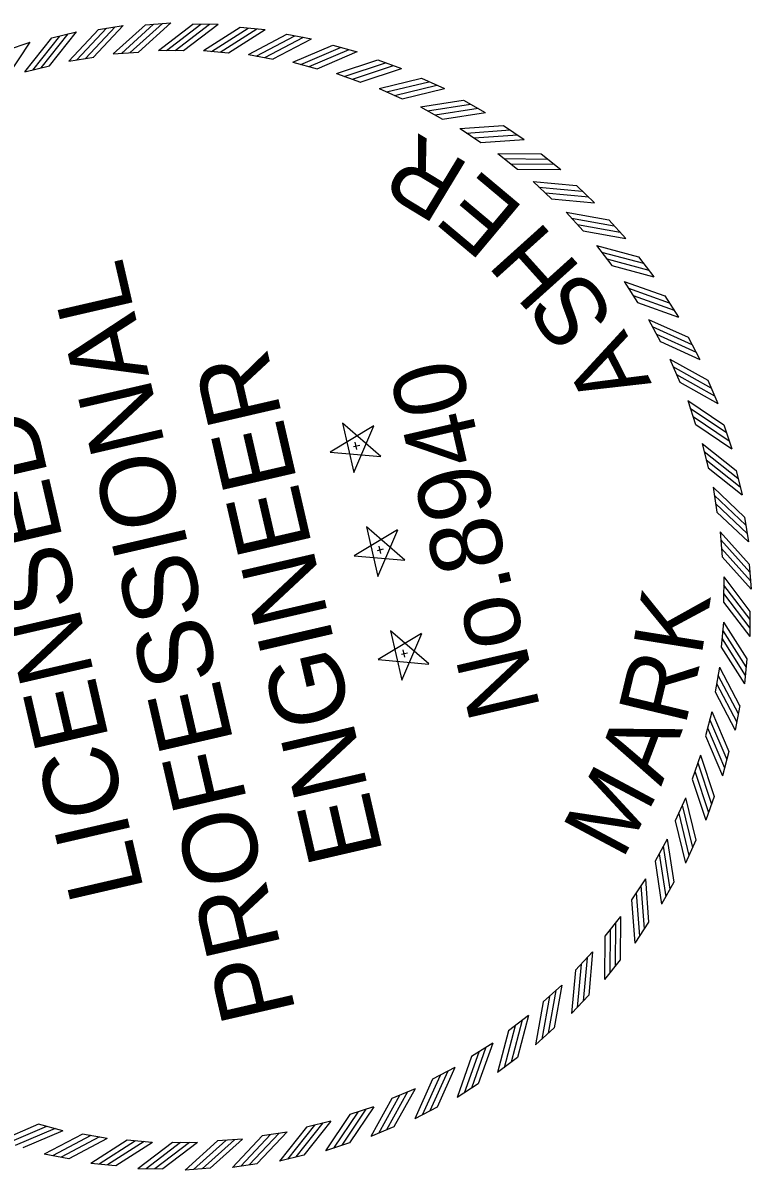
# Model space of a CAD drawing. Extents: x 634644 to 1109508, y 286699 to 700437.
# Drawn here: x 1108220.4 to 1108286.1, y 700312.5 to 700415.8 of the extents above; entities that cross this region are included whole.
import ezdxf

# ---------------------------------------------------------------- set-up
doc = ezdxf.new("R2010")
doc.units = 0
doc.layers.add('R_Border', color=7, linetype='Continuous')

msp = doc.modelspace()

# ---------------------------------------------------------------- linework, layer by layer
at = {"layer": 'R_Border'}
for p, q in [((1108223.06, 700414.47), (1108225.26, 700415)), ((1108227.26, 700415.23), (1108229.49, 700415.58)), ((1108231.5, 700415.65), (1108233.76, 700415.81)), ((1108235.76, 700415.72), (1108238.03, 700415.69)), ((1108240.02, 700415.43), (1108242.27, 700415.21)), ((1108218.95, 700413.36), (1108221.09, 700414.07)), ((1108244.23, 700414.79), (1108246.46, 700414.39)), ((1108228.59, 700413.03), (1108230.85, 700413.19)), ((1108232.65, 700413.35), (1108234.92, 700413.32)), ((1108236.72, 700413.32), (1108238.98, 700413.11)), ((1108240.77, 700412.96), (1108243, 700412.56)), ((1108248.38, 700413.81), (1108250.57, 700413.22)), ((1108220.62, 700411.41), (1108222.83, 700411.94)), ((1108224.57, 700412.38), (1108226.82, 700412.73)), ((1108244.78, 700412.27), (1108246.97, 700411.69)), ((1108252.44, 700412.48), (1108254.57, 700411.72)), ((1108248.72, 700411.25), (1108250.86, 700410.49)), ((1108256.37, 700410.83), (1108258.43, 700409.9)), ((1108252.56, 700409.91), (1108254.63, 700408.97)), ((1108260.15, 700408.86), (1108262.12, 700407.76)), ((1108256.28, 700408.25), (1108258.26, 700407.15)), ((1108259.85, 700406.3), (1108261.73, 700405.04)), ((1108263.75, 700406.58), (1108265.63, 700405.32)), ((1108263.24, 700404.05), (1108265.01, 700402.64)), ((1108267.15, 700404.01), (1108268.92, 700402.6)), ((1108266.44, 700401.54), (1108268.09, 700399.98)), ((1108270.33, 700401.17), (1108271.98, 700399.62)), ((1108269.42, 700398.76), (1108270.93, 700397.08)), ((1108273.27, 700398.08), (1108274.78, 700396.39)), ((1108272.16, 700395.76), (1108273.53, 700393.95)), ((1108275.94, 700394.75), (1108277.31, 700392.95)), ((1108274.64, 700392.53), (1108275.85, 700390.62)), ((1108278.32, 700391.22), (1108279.54, 700389.31)), ((1108276.84, 700389.11), (1108277.9, 700387.1)), ((1108280.41, 700387.5), (1108281.46, 700385.5)), ((1108278.76, 700385.52), (1108279.65, 700383.44)), ((1108282.18, 700383.62), (1108283.07, 700381.54)), ((1108280.37, 700381.79), (1108281.08, 700379.63)), ((1108249.26, 700379.76), (1108250.28, 700375.31)), ((1108252.7, 700376.76), (1108249.26, 700379.76)), ((1108252.07, 700379.51), (1108248.15, 700377.16)), ((1108250.28, 700375.31), (1108252.07, 700379.51)), ((1108283.63, 700379.61), (1108284.34, 700377.46)), ((1108250.24, 700377.65), (1108250.8, 700377.78)), ((1108250.55, 700377.38), (1108250.4, 700378.04)), ((1108281.67, 700377.93), (1108282.2, 700375.73)), ((1108248.15, 700377.16), (1108252.7, 700376.76)), ((1108284.74, 700375.49), (1108285.27, 700373.29)), ((1108282.65, 700373.98), (1108283, 700371.74)), ((1108285.5, 700371.3), (1108285.85, 700369.06)), ((1108254.22, 700370.16), (1108250.31, 700367.81)), ((1108251.41, 700370.41), (1108252.44, 700365.96)), ((1108254.86, 700367.41), (1108251.41, 700370.41)), ((1108252.44, 700365.96), (1108254.23, 700370.16)), ((1108283.3, 700369.96), (1108283.46, 700367.7)), ((1108252.4, 700368.3), (1108252.96, 700368.43)), ((1108252.71, 700368.03), (1108252.56, 700368.69)), ((1108250.31, 700367.81), (1108254.86, 700367.41)), ((1108285.92, 700367.05), (1108286.08, 700364.8)), ((1108283.61, 700365.91), (1108283.59, 700363.64)), ((1108285.98, 700362.79), (1108285.96, 700360.53)), ((1108283.59, 700361.84), (1108283.38, 700359.58)), ((1108256.38, 700360.81), (1108252.47, 700358.46)), ((1108253.57, 700361.06), (1108254.6, 700356.61)), ((1108257.02, 700358.07), (1108253.57, 700361.06)), ((1108254.6, 700356.61), (1108256.39, 700360.81)), ((1108254.56, 700358.95), (1108255.12, 700359.08)), ((1108254.87, 700358.68), (1108254.72, 700359.34)), ((1108252.47, 700358.46), (1108257.02, 700358.06)), ((1108285.69, 700358.54), (1108285.48, 700356.29)), ((1108283.23, 700357.78), (1108282.83, 700355.55)), ((1108285.06, 700354.32), (1108284.66, 700352.1)), ((1108282.54, 700353.77), (1108281.96, 700351.58)), ((1108281.52, 700349.84), (1108280.76, 700347.7)), ((1108284.07, 700350.17), (1108283.49, 700347.99)), ((1108280.18, 700345.99), (1108279.24, 700343.93)), ((1108282.75, 700346.12), (1108281.99, 700343.99)), ((1108278.52, 700342.28), (1108277.42, 700340.3)), ((1108281.1, 700342.19), (1108280.16, 700340.13)), ((1108276.56, 700338.71), (1108275.3, 700336.83)), ((1108279.12, 700338.41), (1108278.02, 700336.43)), ((1108274.32, 700335.32), (1108272.91, 700333.54)), ((1108276.84, 700334.81), (1108275.59, 700332.93)), ((1108271.8, 700332.12), (1108270.25, 700330.47)), ((1108274.28, 700331.4), (1108272.87, 700329.63)), ((1108269.03, 700329.14), (1108267.34, 700327.62)), ((1108271.44, 700328.22), (1108269.89, 700326.58)), ((1108266.02, 700326.4), (1108264.22, 700325.03)), ((1108268.34, 700325.29), (1108266.66, 700323.77)), ((1108262.8, 700323.92), (1108260.88, 700322.7)), ((1108265.02, 700322.62), (1108263.22, 700321.25)), ((1108259.38, 700321.71), (1108257.37, 700320.66)), ((1108255.79, 700319.8), (1108253.7, 700318.91)), ((1108261.49, 700320.23), (1108259.58, 700319.02)), ((1108252.05, 700318.18), (1108249.9, 700317.47)), ((1108257.77, 700318.15), (1108255.76, 700317.09)), ((1108248.2, 700316.88), (1108245.99, 700316.35)), ((1108224.04, 700316.02), (1108221.85, 700316.6)), ((1108228.05, 700315.32), (1108225.82, 700315.72)), ((1108244.25, 700315.9), (1108242.01, 700315.56)), ((1108253.89, 700316.37), (1108251.81, 700315.49)), ((1108232.1, 700314.97), (1108229.85, 700315.18)), ((1108236.17, 700314.94), (1108233.91, 700314.97)), ((1108240.23, 700315.26), (1108237.97, 700315.1)), ((1108249.88, 700314.93), (1108247.73, 700314.22)), ((1108224.59, 700313.5), (1108222.36, 700313.9)), ((1108245.76, 700313.82), (1108243.56, 700313.29)), ((1108228.8, 700312.86), (1108226.55, 700313.08)), ((1108233.06, 700312.57), (1108230.8, 700312.6)), ((1108237.32, 700312.64), (1108235.07, 700312.48)), ((1108241.56, 700313.05), (1108239.33, 700312.71))]:
    msp.add_line(p, q, dxfattribs=at)
for points in [[(1108222.83, 700411.94), (1108225.26, 700415)], [(1108224.57, 700412.38), (1108227.25, 700415.23)], [(1108225.29, 700412.49), (1108227.98, 700415.34)], [(1108226.07, 700412.62), (1108228.75, 700415.47)], [(1108226.81, 700412.73), (1108229.49, 700415.58)], [(1108228.59, 700413.03), (1108231.5, 700415.65)], [(1108229.32, 700413.07), (1108232.22, 700415.69)], [(1108230.1, 700413.15), (1108233.01, 700415.77)], [(1108230.85, 700413.19), (1108233.76, 700415.81)], [(1108232.65, 700413.34), (1108235.76, 700415.71)], [(1108233.37, 700413.33), (1108236.49, 700415.7)], [(1108234.16, 700413.34), (1108237.27, 700415.71)], [(1108234.91, 700413.32), (1108238.03, 700415.69)], [(1108236.72, 700413.32), (1108240.01, 700415.43)], [(1108237.44, 700413.25), (1108240.74, 700415.35)], [(1108238.22, 700413.19), (1108241.52, 700415.29)], [(1108238.97, 700413.11), (1108242.27, 700415.22)], [(1108218.92, 700410.82), (1108221.1, 700414.07)], [(1108220.62, 700411.4), (1108223.06, 700414.47)], [(1108221.33, 700411.57), (1108223.77, 700414.63)], [(1108222.09, 700411.77), (1108224.53, 700414.83)], [(1108240.77, 700412.96), (1108244.23, 700414.79)], [(1108241.48, 700412.83), (1108244.95, 700414.65)], [(1108242.26, 700412.71), (1108245.72, 700414.53)], [(1108243, 700412.57), (1108246.46, 700414.39)], [(1108244.78, 700412.27), (1108248.38, 700413.8)], [(1108245.48, 700412.08), (1108249.08, 700413.61)], [(1108246.24, 700411.89), (1108249.84, 700413.43)], [(1108246.97, 700411.69), (1108250.57, 700413.23)], [(1108248.72, 700411.25), (1108252.43, 700412.48)], [(1108249.4, 700411), (1108253.12, 700412.23)], [(1108250.15, 700410.75), (1108253.86, 700411.98)], [(1108250.85, 700410.49), (1108254.57, 700411.72)], [(1108252.56, 700409.91), (1108256.36, 700410.83)], [(1108253.22, 700409.6), (1108257.02, 700410.52)], [(1108253.94, 700409.29), (1108257.75, 700410.21)], [(1108254.62, 700408.98), (1108258.43, 700409.9)], [(1108256.28, 700408.25), (1108260.14, 700408.86)], [(1108256.91, 700407.89), (1108260.78, 700408.5)], [(1108257.6, 700407.53), (1108261.47, 700408.13)], [(1108258.26, 700407.15), (1108262.13, 700407.76)], [(1108259.84, 700406.3), (1108263.75, 700406.58)], [(1108260.44, 700405.89), (1108264.35, 700406.17)], [(1108261.11, 700405.46), (1108265.01, 700405.74)], [(1108261.73, 700405.04), (1108265.63, 700405.32)], [(1108263.24, 700404.05), (1108267.15, 700404.01)], [(1108263.8, 700403.59), (1108267.72, 700403.55)], [(1108264.43, 700403.12), (1108268.34, 700403.08)], [(1108265.01, 700402.64), (1108268.93, 700402.6)], [(1108266.43, 700401.54), (1108270.33, 700401.17)], [(1108266.96, 700401.03), (1108270.86, 700400.67)], [(1108267.54, 700400.51), (1108271.44, 700400.14)], [(1108268.09, 700399.98), (1108271.98, 700399.62)], [(1108269.41, 700398.76), (1108273.27, 700398.08)], [(1108269.89, 700398.22), (1108273.75, 700397.53)], [(1108270.43, 700397.65), (1108274.29, 700396.96)], [(1108270.93, 700397.08), (1108274.78, 700396.39)], [(1108272.15, 700395.76), (1108275.94, 700394.75)], [(1108272.59, 700395.17), (1108276.37, 700394.17)], [(1108273.08, 700394.56), (1108276.86, 700393.55)], [(1108273.53, 700393.95), (1108277.31, 700392.95)], [(1108274.63, 700392.53), (1108278.32, 700391.22)], [(1108275.02, 700391.91), (1108278.71, 700390.6)], [(1108275.46, 700391.26), (1108279.14, 700389.95)], [(1108275.85, 700390.62), (1108279.54, 700389.31)], [(1108276.84, 700389.11), (1108280.41, 700387.5)], [(1108277.17, 700388.47), (1108280.74, 700386.85)], [(1108277.55, 700387.78), (1108281.12, 700386.17)], [(1108277.9, 700387.11), (1108281.47, 700385.5)], [(1108278.76, 700385.52), (1108282.18, 700383.62)], [(1108279.04, 700384.85), (1108282.46, 700382.95)], [(1108279.36, 700384.13), (1108282.78, 700382.23)], [(1108279.65, 700383.44), (1108283.07, 700381.54)], [(1108280.37, 700381.79), (1108283.62, 700379.61)], [(1108280.59, 700381.1), (1108283.85, 700378.92)], [(1108280.86, 700380.35), (1108284.11, 700378.18)], [(1108281.09, 700379.64), (1108284.34, 700377.46)], [(1108281.67, 700377.93), (1108284.73, 700375.5)], [(1108281.84, 700377.22), (1108284.9, 700374.79)], [(1108282.04, 700376.46), (1108285.1, 700374.03)], [(1108282.21, 700375.73), (1108285.27, 700373.29)], [(1108282.65, 700373.98), (1108285.5, 700371.3)], [(1108282.75, 700373.26), (1108285.6, 700370.58)], [(1108282.89, 700372.49), (1108285.74, 700369.81)], [(1108283, 700371.74), (1108285.85, 700369.06)], [(1108283.3, 700369.97), (1108285.92, 700367.06)], [(1108283.34, 700369.24), (1108285.96, 700366.33)], [(1108283.41, 700368.46), (1108286.03, 700365.55)], [(1108283.46, 700367.71), (1108286.08, 700364.8)], [(1108283.61, 700365.91), (1108285.98, 700362.79)], [(1108283.59, 700365.18), (1108285.96, 700362.07)], [(1108283.6, 700364.4), (1108285.97, 700361.28)], [(1108283.59, 700363.64), (1108285.96, 700360.53)], [(1108283.59, 700361.84), (1108285.69, 700358.54)], [(1108283.46, 700360.33), (1108285.56, 700357.03)], [(1108283.51, 700361.12), (1108285.62, 700357.82)], [(1108283.38, 700359.58), (1108285.48, 700356.28)], [(1108283.09, 700357.07), (1108284.92, 700353.61)], [(1108283.23, 700357.79), (1108285.05, 700354.33)], [(1108282.97, 700356.3), (1108284.8, 700352.83)], [(1108282.83, 700355.56), (1108284.66, 700352.09)], [(1108282.34, 700353.08), (1108283.88, 700349.47)], [(1108282.54, 700353.78), (1108284.07, 700350.18)], [(1108282.16, 700352.31), (1108283.69, 700348.71)], [(1108281.96, 700351.59), (1108283.49, 700347.98)], [(1108281.52, 700349.84), (1108282.75, 700346.12)], [(1108281.27, 700349.16), (1108282.5, 700345.44)], [(1108280.76, 700347.7), (1108281.99, 700343.99)], [(1108281.02, 700348.41), (1108282.25, 700344.69)], [(1108280.18, 700346), (1108281.09, 700342.19)], [(1108279.56, 700344.61), (1108280.48, 700340.81)], [(1108279.87, 700345.34), (1108280.79, 700341.53)], [(1108279.24, 700343.93), (1108280.16, 700340.13)], [(1108278.16, 700341.65), (1108278.76, 700337.78)], [(1108278.52, 700342.28), (1108279.12, 700338.41)], [(1108277.79, 700340.95), (1108278.4, 700337.09)], [(1108277.42, 700340.3), (1108278.02, 700336.43)], [(1108276.56, 700338.71), (1108276.84, 700334.81)], [(1108275.73, 700337.45), (1108276.01, 700333.55)], [(1108276.15, 700338.11), (1108276.43, 700334.21)], [(1108275.3, 700336.83), (1108275.59, 700332.92)], [(1108274.32, 700335.32), (1108274.28, 700331.41)], [(1108273.86, 700334.75), (1108273.82, 700330.84)], [(1108272.91, 700333.54), (1108272.87, 700329.63)], [(1108273.38, 700334.13), (1108273.34, 700330.22)], [(1108271.3, 700331.6), (1108270.93, 700327.7)], [(1108271.8, 700332.12), (1108271.44, 700328.22)], [(1108270.25, 700330.47), (1108269.88, 700326.57)], [(1108270.77, 700331.01), (1108270.41, 700327.12)], [(1108269.03, 700329.14), (1108268.34, 700325.29)], [(1108267.91, 700328.12), (1108267.23, 700324.27)], [(1108268.49, 700328.66), (1108267.8, 700324.81)], [(1108267.35, 700327.62), (1108266.66, 700323.77)], [(1108266.02, 700326.4), (1108265.02, 700322.62)], [(1108264.22, 700325.03), (1108263.22, 700321.25)], [(1108264.82, 700325.48), (1108263.82, 700321.7)], [(1108265.44, 700325.97), (1108264.44, 700322.19)], [(1108261.53, 700323.1), (1108260.22, 700319.41)], [(1108262.18, 700323.54), (1108260.87, 700319.85)], [(1108262.8, 700323.92), (1108261.49, 700320.23)], [(1108260.89, 700322.7), (1108259.58, 700319.01)], [(1108258.04, 700321), (1108256.43, 700317.43)], [(1108258.73, 700321.38), (1108257.12, 700317.82)], [(1108259.38, 700321.72), (1108257.77, 700318.15)], [(1108255.79, 700319.8), (1108253.89, 700316.38)], [(1108257.37, 700320.66), (1108255.76, 700317.09)], [(1108253.7, 700318.91), (1108251.8, 700315.49)], [(1108254.4, 700319.2), (1108252.5, 700315.78)], [(1108255.12, 700319.52), (1108253.22, 700316.1)], [(1108251.36, 700317.96), (1108249.19, 700314.71)], [(1108252.06, 700318.18), (1108249.88, 700314.93)], [(1108247.49, 700316.72), (1108245.05, 700313.66)], [(1108248.2, 700316.88), (1108245.76, 700313.82)], [(1108249.9, 700317.47), (1108247.73, 700314.22)], [(1108250.62, 700317.7), (1108248.44, 700314.45)], [(1108221.85, 700316.6), (1108218.25, 700315.06)], [(1108222.58, 700316.4), (1108218.98, 700314.86)], [(1108223.34, 700316.21), (1108219.74, 700314.68)], [(1108224.04, 700316.02), (1108220.44, 700314.49)], [(1108225.82, 700315.72), (1108222.36, 700313.9)], [(1108242.76, 700315.67), (1108240.07, 700312.82)], [(1108243.53, 700315.8), (1108240.85, 700312.95)], [(1108244.25, 700315.91), (1108241.57, 700313.06)], [(1108246, 700316.35), (1108243.56, 700313.29)], [(1108246.73, 700316.52), (1108244.29, 700313.46)], [(1108226.56, 700315.58), (1108223.1, 700313.76)], [(1108227.34, 700315.46), (1108223.88, 700313.64)], [(1108228.05, 700315.33), (1108224.59, 700313.5)], [(1108229.85, 700315.18), (1108226.55, 700313.07)], [(1108230.6, 700315.1), (1108227.3, 700313)], [(1108231.38, 700315.04), (1108228.08, 700312.94)], [(1108232.11, 700314.97), (1108228.81, 700312.86)], [(1108233.91, 700314.97), (1108230.79, 700312.6)], [(1108234.66, 700314.95), (1108231.55, 700312.58)], [(1108235.45, 700314.96), (1108232.33, 700312.59)], [(1108236.18, 700314.95), (1108233.06, 700312.58)], [(1108237.97, 700315.1), (1108235.06, 700312.48)], [(1108238.72, 700315.14), (1108235.82, 700312.52)], [(1108239.51, 700315.21), (1108236.6, 700312.6)], [(1108240.23, 700315.26), (1108237.32, 700312.64)], [(1108242.01, 700315.56), (1108239.33, 700312.71)]]:
    msp.add_lwpolyline(points, dxfattribs=at)

# ---------------------------------------------------------------- texts
for s, height, rotation, p in [('R', 6.25, 148.7825, (1108260.89, 700402.95)), ('E', 6.25, 140.0272, (1108265.77, 700399.03)), ('H', 6.25, 132.0016, (1108270.9, 700393.65)), ('PROFESSIONAL', 6.7161, 103, (1108245.07, 700326.71)), ('S', 6.25, 124.7056, (1108273.98, 700389.26)), ('A', 6.25, 117.0448, (1108277.15, 700383.36)), ('ENGINEER', 6.716, 103, (1108252.93, 700341)), ('No.8940', 6.476, 103, (1108267.12, 700354)), ('LICENSED', 6.716, 103, (1108231.38, 700337.66)), ('K', 6.25, 80.9296, (1108281.6, 700358.67)), ('R', 6.25, 76.552, (1108280.13, 700352.38)), ('A', 6.25, 69.256, (1108277.97, 700346.99)), ('M', 6.25, 61.9599, (1108274.45, 700340.32))]:
    msp.add_text(s, height=height, rotation=rotation, dxfattribs=at).set_placement(p)

doc.saveas('drawing.dxf')
